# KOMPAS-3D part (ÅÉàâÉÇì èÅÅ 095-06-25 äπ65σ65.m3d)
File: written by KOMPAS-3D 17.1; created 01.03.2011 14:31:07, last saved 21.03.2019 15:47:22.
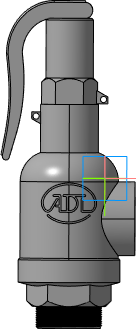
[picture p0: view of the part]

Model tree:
1. Операция без истории:1

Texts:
  Viktor2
